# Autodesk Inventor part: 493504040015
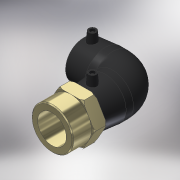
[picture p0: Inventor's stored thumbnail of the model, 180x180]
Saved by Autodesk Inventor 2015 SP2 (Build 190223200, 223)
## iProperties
Created: 2017-06
Part Number: 493504040015
Material: Generic
Description: PLASSON 90° ELBOW FEMALE TRANSITION 40-1.1/2''
Document SubType Name: Modeling
Designer: KIM
Mass: 201.458 g
Surface Area: 513.664 cm^2
Volume: 201.458 cm^3
Density: 1 g/cm^3
Appearance: Rubber - Black
Author: KIM
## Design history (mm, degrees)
derived "493504.ipt"
feature "Solid1::493504.ipt"
tag "TaggingFeature1"
body "Solid1"
other parameters: "d2" = 56, "d4" = 30.66667, "d5" = 50.4, "d8" = 168 deg, "d10" = 17.6, "d11" = 5.86667, "d29" = 47, "d30" = 15, "d31" = 50.6, "d34" = 5 deg, "d41" = 4, "d42" = 14, "d43" = 0, "d48" = 64, "d50" = 34, "d51" = 17.6, "d52" = 44, "d54" = 90 deg, "d58" = 44, "d59" = 0, "d61" = 90 deg, "d86" = 3, "d87" = 0, "d93" = 0.1, "d96" = 44.845, "d97" = 29, "d98" = 25, "d99" = 56, "d108" = 0, "d109" = 1.2, "d112" = 45 deg, "d113" = 45 deg, "d114" = 2, "L_" = 117, "L_1" = 44, "D_" = 29, "A_" = 47, "d_2" = 12, "L_2" = 25, "D_1" = 56, "Rp_" = 44.845
